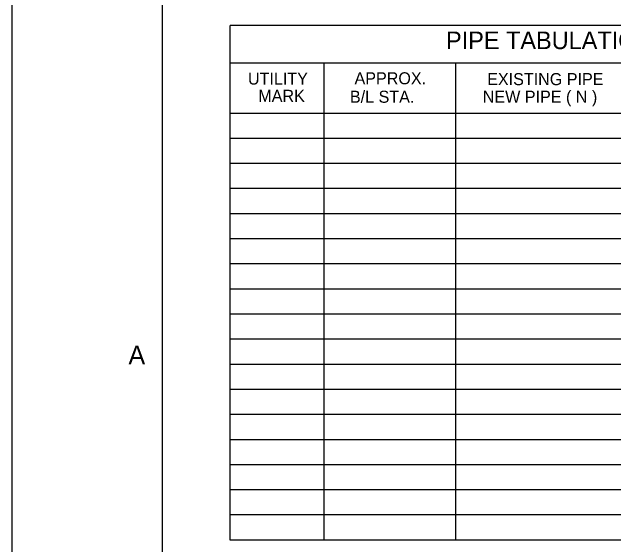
# Model space of a CAD drawing. Extents: x 22422.9 to 22498.9, y 22369.6 to 22415.
# Drawn here: x 22440.26 to 22448.26, y 22373.26 to 22380.33 of the extents above; entities that cross this region are included whole.
import ezdxf

# ---------------------------------------------------------------- set-up
doc = ezdxf.new("R2010")
doc.units = 0
for name, color, linetype in [('Level 1', 7, 'Continuous'), ('Level 2', 7, 'Continuous'), ('Level 4', 7, 'Continuous'), ('Level 7', 7, 'Continuous'), ('Level 9', 7, 'Continuous')]:
    doc.layers.add(name, color=color, linetype=linetype)

msp = doc.modelspace()

# ---------------------------------------------------------------- linework, layer by layer
at = {"layer": 'Level 1'}
msp.add_lwpolyline([(22440.2597, 22414.9653), (22498.9269, 22414.9653), (22498.9269, 22369.6213), (22440.2597, 22369.6213)], close=True, dxfattribs=at)
at = {"layer": 'Level 2'}
for p, q in [((22454.9076, 22378.6537), (22443.1576, 22378.6537)), ((22454.9076, 22378.3204), (22443.1576, 22378.3204)), ((22454.9076, 22377.9871), (22443.1576, 22377.9871)), ((22454.9076, 22377.6537), (22443.1576, 22377.6537)), ((22454.9076, 22377.3204), (22443.1576, 22377.3204)), ((22454.9076, 22376.9871), (22443.1576, 22376.9871)), ((22454.9076, 22376.6537), (22443.1576, 22376.6537)), ((22454.9076, 22376.3204), (22443.1576, 22376.3204)), ((22454.9076, 22375.9871), (22443.1576, 22375.9871)), ((22454.9076, 22375.6537), (22443.1576, 22375.6537)), ((22454.9076, 22375.3204), (22443.1576, 22375.3204)), ((22454.9076, 22374.9871), (22443.1576, 22374.9871)), ((22454.9076, 22374.6537), (22443.1576, 22374.6537)), ((22454.9076, 22374.3204), (22443.1576, 22374.3204)), ((22454.9076, 22373.9871), (22443.1576, 22373.9871)), ((22454.9076, 22373.6537), (22443.1576, 22373.6537))]:
    msp.add_line(p, q, dxfattribs=at)
at = {"layer": 'Level 7'}
for p, q in [((22454.9076, 22380.1537), (22443.1576, 22380.1537)), ((22443.1576, 22373.3204), (22443.1576, 22380.1537)), ((22454.9076, 22379.6537), (22443.1576, 22379.6537)), ((22444.4076, 22373.3204), (22444.4076, 22379.6537)), ((22446.1576, 22373.3204), (22446.1576, 22379.6537)), ((22454.9076, 22378.9871), (22443.1576, 22378.9871)), ((22454.9076, 22373.3204), (22443.1576, 22373.3204))]:
    msp.add_line(p, q, dxfattribs=at)
at = {"layer": 'Level 9'}
msp.add_line((22442.2597, 22370.2933), (22442.2597, 22414.2933), dxfattribs=at)

# ---------------------------------------------------------------- texts
at = {"layer": 'Level 1'}
msp.add_text('A', height=0.2497, dxfattribs=at).set_placement((22441.8069, 22375.6533))
at = {"layer": 'Level 4'}
for s, height, p in [('PIPE TABULATION AND SLEEVE TABLE', 0.233333, (22446.0276, 22379.8398)), ('UTILITY', 0.16, (22443.3953, 22379.3685)), ('APPROX.', 0.16, (22444.8117, 22379.3726)), ('EXISTING PIPE', 0.16, (22446.5747, 22379.3614)), ('MARK', 0.16, (22443.5329, 22379.1395)), ('B/L STA.', 0.16, (22444.7506, 22379.1276)), ('NEW PIPE ( N )', 0.16, (22446.5165, 22379.1277))]:
    msp.add_text(s, height=height, dxfattribs=at).set_placement(p)

doc.saveas('drawing.dxf')
